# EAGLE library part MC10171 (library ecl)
Dual BINARY To 1-4 Decoder (Low)
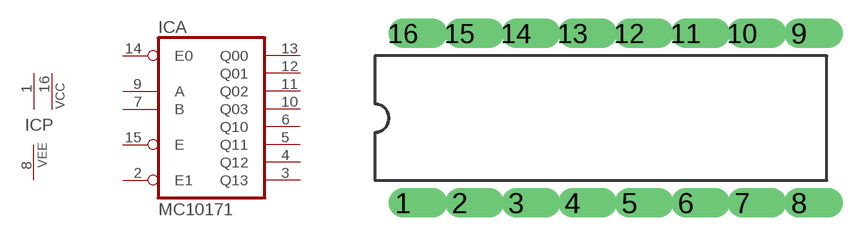
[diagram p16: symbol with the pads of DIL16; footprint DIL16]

Designator prefix IC; gates A=MC10171 P=2VCC1VEE

## MC10171  [DIL16]
1  P:VCC  pwr
2  A:E1  in
3  A:Q13  out
4  A:Q12  out
5  A:Q11  out
6  A:Q10  out
7  A:B  in
8  P:VEE  pwr
9  A:A  in
10  A:Q03  out
11  A:Q02  out
12  A:Q01  out
13  A:Q00  out
14  A:E0  in
15  A:E  in
16  P:VCC  pwr

## Footprint DIL16 (pad centres in mm)
drill 0.813 offset: 1 -8.89,-3.81; 2 -6.35,-3.81; 3 -3.81,-3.81; 4 -1.27,-3.81; 5 1.27,-3.81; 6 3.81,-3.81; 7 6.35,-3.81; 8 8.89,-3.81; 9 8.89,3.81; 10 6.35,3.81; 11 3.81,3.81; 12 1.27,3.81; 13 -1.27,3.81; 14 -3.81,3.81; 15 -6.35,3.81; 16 -8.89,3.81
